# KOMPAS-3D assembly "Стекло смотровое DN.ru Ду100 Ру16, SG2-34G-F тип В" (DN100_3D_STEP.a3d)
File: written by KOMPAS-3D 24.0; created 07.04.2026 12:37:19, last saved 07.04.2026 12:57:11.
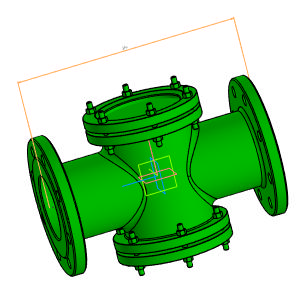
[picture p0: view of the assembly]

Document properties: Автор: Main; Полное имя файла: D:\DN.ru Аутсерс\Стекло смотровое DN.ru\Исходники\Стекло смотровое DN.ru SG2-34G-F тип В ГОСТ 21836-2021 Ду100 Ру16, углеродистая сталь, фланцевое\DN100_3D_STEP.a3d

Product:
- Component [detail]: Деталь  | qty 1  | pos. 1  | Масса: 23.811038; Автор: Main; additional columns: Типовые; source file: ДетальДеталь.m3d
- Component [detail]: Стекло  | qty 2  | pos. 2  | Масса: 1.042745; Автор: Main; source file: СтеклоСтекло.m3d
- Component [detail]: ANSI B18.2.4.2M - M8x1,25 - 13  | designation ANSI B18.2.4.2M - M8x1,25  | qty 24  | pos. 3  | Масса: 0.006562; Комментарий: Типы метрических   шестигранных гаек   2; Автор: Main; additional columns: Сталь, мягкая; source file: ANSI B18.2.4.2M - M8x1,25ANSI B18.2.4.2M - M8x1,25 - 13.m3d
- Part/product: Стекло смотровое DN.ru Ду100 Ру16  | designation SG2-34G-F тип В
    Масса: 260
    Раздел спецификации: Прочие изделия
    Примечание: D500-00087

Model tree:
1. Линейный размер:1  (labels: Грань.Твердое тело1; Ребро.Твердое тело1; Ребро.Solid1; Грань.Solid1)
     Значение = 350

Referenced files in D:\DN.ru Аутсерс\Стекло смотровое DN.ru\Исходники\Стекло смотровое DN.ru SG2-34G-F тип В ГОСТ 21836-2021 Ду100 Ру16, углеродистая сталь, фланцевое\: ДетальДеталь.m3d, СтеклоСтекло.m3d, ANSI B18.2.4.2M - M8x1,25ANSI B18.2.4.2M - M8x1,25 - 13.m3d
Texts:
  Точка начала. Х
  Точка начала. Y
  Точка начала. Z
  SG2-34G-F тип В
  Стекло Стекло (1)
  Стекло Стекло (2)
  ANSI B18.2.4.2M - M8x1,25 ANSI B18.2.4.2M - M8x1,25 - 13 (1)
  ANSI B18.2.4.2M - M8x1,25 ANSI B18.2.4.2M - M8x1,25 - 13 (2)
  ANSI B18.2.4.2M - M8x1,25 ANSI B18.2.4.2M - M8x1,25 - 13 (3)
  ANSI B18.2.4.2M - M8x1,25 ANSI B18.2.4.2M - M8x1,25 - 13 (4)
  ANSI B18.2.4.2M - M8x1,25 ANSI B18.2.4.2M - M8x1,25 - 13 (5)
  ANSI B18.2.4.2M - M8x1,25 ANSI B18.2.4.2M - M8x1,25 - 13 (6)
  ANSI B18.2.4.2M - M8x1,25 ANSI B18.2.4.2M - M8x1,25 - 13 (7)
  ANSI B18.2.4.2M - M8x1,25 ANSI B18.2.4.2M - M8x1,25 - 13 (8)
  ANSI B18.2.4.2M - M8x1,25 ANSI B18.2.4.2M - M8x1,25 - 13 (9)
  ANSI B18.2.4.2M - M8x1,25 ANSI B18.2.4.2M - M8x1,25 - 13 (10)
  ANSI B18.2.4.2M - M8x1,25 ANSI B18.2.4.2M - M8x1,25 - 13 (11)
  ANSI B18.2.4.2M - M8x1,25 ANSI B18.2.4.2M - M8x1,25 - 13 (12)
  ANSI B18.2.4.2M - M8x1,25 ANSI B18.2.4.2M - M8x1,25 - 13 (13)
  ANSI B18.2.4.2M - M8x1,25 ANSI B18.2.4.2M - M8x1,25 - 13 (14)
  ANSI B18.2.4.2M - M8x1,25 ANSI B18.2.4.2M - M8x1,25 - 13 (15)
  ANSI B18.2.4.2M - M8x1,25 ANSI B18.2.4.2M - M8x1,25 - 13 (16)
  ANSI B18.2.4.2M - M8x1,25 ANSI B18.2.4.2M - M8x1,25 - 13 (17)
  ANSI B18.2.4.2M - M8x1,25 ANSI B18.2.4.2M - M8x1,25 - 13 (18)
  ANSI B18.2.4.2M - M8x1,25 ANSI B18.2.4.2M - M8x1,25 - 13 (19)
  ANSI B18.2.4.2M - M8x1,25 ANSI B18.2.4.2M - M8x1,25 - 13 (20)
  ANSI B18.2.4.2M - M8x1,25 ANSI B18.2.4.2M - M8x1,25 - 13 (21)
  ANSI B18.2.4.2M - M8x1,25 ANSI B18.2.4.2M - M8x1,25 - 13 (22)
  ANSI B18.2.4.2M - M8x1,25 ANSI B18.2.4.2M - M8x1,25 - 13 (23)
  ANSI B18.2.4.2M - M8x1,25 ANSI B18.2.4.2M - M8x1,25 - 13 (24)
  Ось Z.Начало координат
  Ось X.Начало координат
